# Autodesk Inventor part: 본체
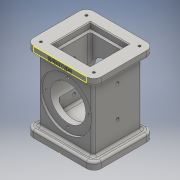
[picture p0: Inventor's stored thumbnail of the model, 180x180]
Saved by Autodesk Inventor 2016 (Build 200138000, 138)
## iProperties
Created: 2017-08
Part Number: 본체
Material: 일반
Document SubType Name: Modeling
Designer: USER
Density: 1 g/cm^3
Appearance: 기본값
Mass: 321.49 g
Surface Area: 645.61 cm^2
Volume: 321.49 cm^3
Author: USER
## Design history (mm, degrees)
sketch "스케치1"
  geometry: L1 (-46, -41)-(46, -41); L2 (46, -41)-(46, 41); L3 (46, 41)-(-46, 41); L4 (-46, 41)-(-46, -41); L5 (-46, -41)-(46, 41); L6 (46, -41)-(-46, 41); 1 further point
  constraints: 12 end point, 2 midpoint, 2 parallel, 1 horizontal, 1 perpendicular
  dimensions: "d0" = 92 distance of L2.end L3.end; "d1" = 82 distance of L1.end L2.end
extrude "돌출1" new body sketch "스케치1" distance "d2" = 10; taper "d3" = 0 deg
sketch "스케치2"
  geometry: L1 (-46, -41)-(46, -41) reference; L2 (46, -41)-(46, 41) reference; L3 (46, 41)-(-46, 41) reference; L4 (-46, 41)-(-46, -41) reference; L5 (-37, 33)-(37, 33); L6 (37, 33)-(37, -33); L7 (37, -33)-(-37, -33); L8 (-37, -33)-(-37, 33); L9 (-37, 33)-(37, -33); L10 (37, 33)-(-37, -33); 1 further point
  constraints: 12 end point, 2 midpoint, 2 parallel, 1 horizontal, 1 perpendicular
  dimensions: "d4" = 74 distance of L5.start L5.end; "d5" = 66 distance of L5.end L6.end
extrude "돌출2" join sketch "스케치2" distance "d6" = 88; taper "d7" = 0 deg
sketch "스케치3"
  geometry: L1 (46, -41)-(46, 41) reference; L2 (-46, -41)-(46, -41); L3 (46, -41)-(46, 41); L4 (46, 41)-(-46, 41); L5 (-46, 41)-(-46, -41); L6 (-46, -41)-(46, 41); L7 (46, -41)-(-46, 41); 1 further point
  constraints: 12 end point, 2 midpoint, 2 parallel, 1 horizontal, 1 perpendicular
extrude "돌출3" join sketch "스케치3" distance "d8" = 10; taper "d9" = 0 deg
sketch "스케치5"
  geometry: L1 (-9, -10)-(83, -10) reference; L2 (-9, 98)-(83, 98) reference; C1 r 35 at (37, 44); 2 further points
  constraints: 1 centre point, 1 midpoint, 1 vertical alignment
  dimensions: "d10" = 70 diameter of C1; "d11" = 54 distance from line of L1 C1.centre
extrude "돌출4" cut sketch "스케치5" distance "d12" = 3; taper "d13" = 0 deg
sketch "스케치6"
  geometry: C1 r 35 at (0, 0) reference; C2 r 24 at (0, 0); 1 further point
  constraints: 1 centre point, 1 coincident
  dimensions: "d14" = 48 diameter of C2
extrude "돌출5" cut sketch "스케치6" stored distance "d15" = 3; taper "d16" = 0 deg
sketch "스케치7"
  geometry: L1 (24, 24)-(-24, 24); L2 (-24, 24)-(-24, -24); L3 (-24, -24)-(24, -24); L4 (24, -24)-(24, 24); L5 (24, 24)-(-24, -24); L6 (-24, 24)-(24, -24); 1 further point
  constraints: 12 end point, 2 midpoint, 2 parallel, 1 horizontal, 1 perpendicular
  dimensions: "d17" = 48 distance of L2.end L3.end; "d18" = 48 distance of L1.end L2.end
extrude "돌출6" cut sketch "스케치7" distance "d19" = 16; taper "d20" = 0 deg
sketch "스케치8"
  geometry: L1 (-26, 26)-(26, 26); L2 (26, 26)-(26, -26); L3 (26, -26)-(-26, -26); L4 (-26, -26)-(-26, 26); L5 (-26, 26)-(26, -26); L6 (26, 26)-(-26, -26); 1 further point
  constraints: 12 end point, 2 midpoint, 2 parallel, 1 horizontal, 1 perpendicular
  dimensions: "d21" = 52 distance of L1.start L1.end; "d22" = 52 distance of L1.end L2.end
extrude "돌출7" cut sketch "스케치8" distance "d23" = 8; taper "d24" = 0 deg
sketch "스케치9"
  geometry: L1 (-22, 22)-(22, 22); L2 (22, 22)-(22, -22); L3 (22, -22)-(-22, -22); L4 (-22, -22)-(-22, 22); L5 (-22, 22)-(22, -22); L6 (22, 22)-(-22, -22); 1 further point
  constraints: 12 end point, 2 midpoint, 2 parallel, 1 horizontal, 1 perpendicular
  dimensions: "d25" = 44 distance of L1.start L1.end; "d26" = 44 distance of L1.end L2.end
extrude "돌출8" cut sketch "스케치9" distance "d27" = 74; taper "d28" = 0 deg
sketch "스케치10"
  geometry: 5 further points
  constraints: 2 horizontal alignment, 2 vertical alignment
  dimensions: "d29" = 72 distance of point (36, 31) point (-36, 31); "d30" = 36 horizontal distance of point (0, 0) point (-36, 31); "d31" = 62 distance of point (36, -31) point (36, 31); "d32" = 31 vertical distance of point (0, 0) point (36, 31)
hole "구멍1" sketch "스케치10" at (-36, 31), (36, 31), (36, -31), (-36, -31) diameter "d33" = 3.242; stored, may be unused: countersink angle "d37" = 90 deg, drill point angle "d39" = 118 deg; dims "d34" = 4, "d35" = 4, "d36" = 2, "d38" = 6
node "작업 평면1"
sketch "스케치11"
  geometry: C1 r 24 at (0, 0) reference; 2 further points
  constraints: 1 vertical alignment
  dimensions: "d41" = 29 distance of C1.centre point (0, 29)
hole "구멍2" sketch "스케치11" at (0, 29) diameter "d42" = 3.242; stored, may be unused: countersink angle "d46" = 90 deg, drill point angle "d48" = 118 deg; dims "d43" = 4, "d44" = 4, "d45" = 2, "d47" = 6
chamfer "모따기1" distance "d65" = 1; stored, may be unused: second distance "d66" = 2, angle "d67" = 45 deg
chamfer "모따기2" distance "d68" = 1; stored, may be unused: second distance "d69" = 2, angle "d70" = 45 deg
chamfer "모따기3" distance "d71" = 1; stored, may be unused: second distance "d72" = 2, angle "d73" = 45 deg
chamfer "모따기4" distance "d74" = 1; stored, may be unused: second distance "d75" = 2, angle "d76" = 45 deg
fillet "모깎기1" dims "d77" = 10
fillet "모깎기2" dims "d78" = 3
fillet "모깎기3" dims "d79" = 3
fillet "모깎기4" dims "d80" = 3
sketch "스케치14"
  geometry: L1 (72, -7)-(0, -7) reference; L2 (72, 0)-(72, -7) reference; L3 (0, 0)-(72, 0) reference; L4 (0, -7)-(0, 0) reference; 1 further point
sketch "스케치15"
  geometry: L1 (0, 0)-(0, 60) reference; L2 (95, -1)-(95, 61) reference; 4 further points
  constraints: 2 horizontal alignment, 1 midpoint
  dimensions: "d81" = 38 distance from line of L2 point (57, 30); "d82" = 42 distance of point (57, 30) point (15, 30)
hole "구멍4" sketch "스케치15" at (15, 30), (57, 30) diameter "d83" = 4.134; stored, may be unused: countersink angle "d87" = 90 deg, drill point angle "d89" = 118 deg; dims "d84" = 74, "d85" = 4, "d86" = 2, "d88" = 14.2
sketch "스케치16"
  geometry: L1 (0, 0)-(72, 0) reference; L2 (-10, 0)-(-10, -7) reference; 2 further points
  constraints: 1 other
  dimensions: "d90" = 46 distance from line of L2 point (36, -4); "d91" = 4 distance from line of L1 point (36, -4)
feature "엠보싱2" sketch "스케치16" dims "d0" = 92, "d1" = 82, "d92" = 0.5, "d93" = 0
node "솔리드1"
mirror "대칭1"
mirror "대칭2"
pattern_circular "원형 패턴1" dims angle "d50" = 360 deg
mirror "대칭3"
node "투영된 루프1"
other parameters: "d40" = 54
